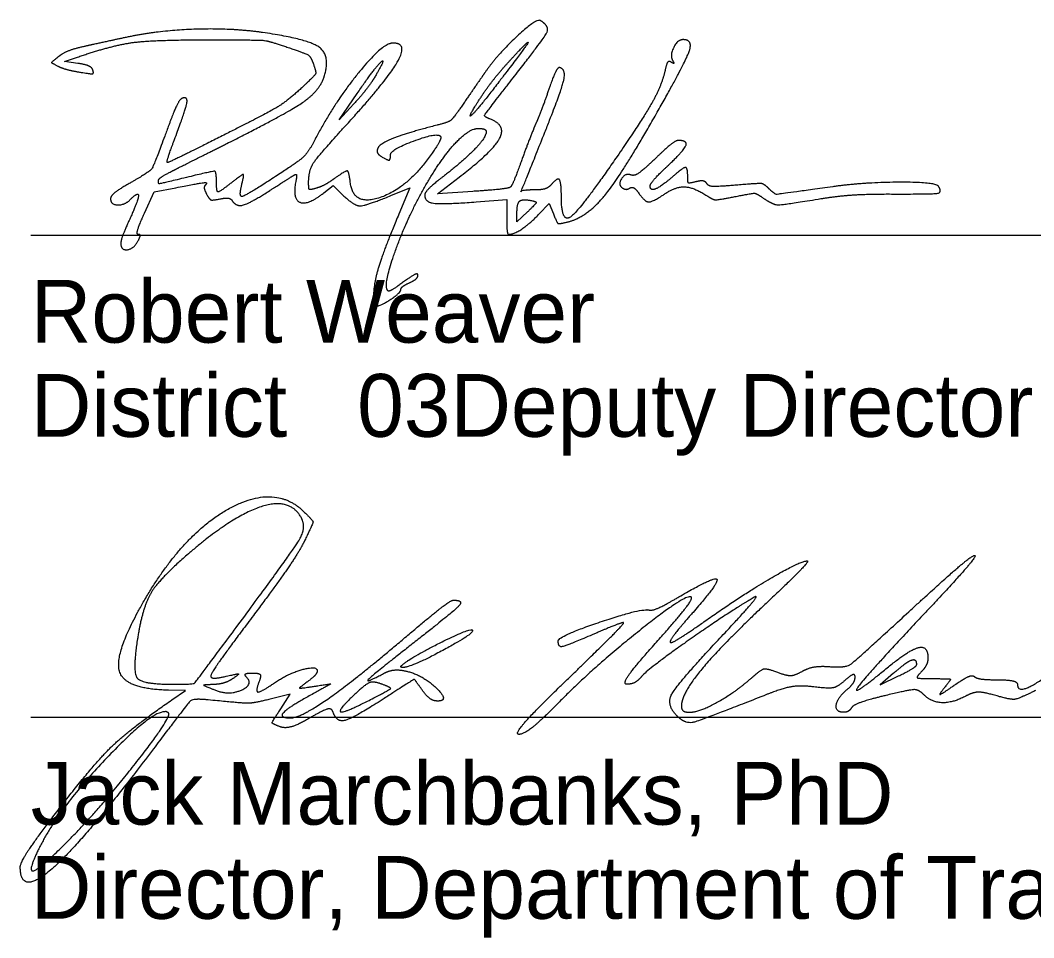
# Model space of a CAD drawing. Extents: x 0 to 34, y 0 to 22.
# Drawn here: x 24.504 to 26.766, y 6.683 to 8.729 of the extents above; entities that cross this region are included whole.
import ezdxf

# ---------------------------------------------------------------- set-up
doc = ezdxf.new("R2010")
doc.units = 0
doc.layers.add('SH_Data', color=7, linetype='Continuous')
doc.layers.add('SH_Text', color=7, linetype='Continuous')

msp = doc.modelspace()

# ---------------------------------------------------------------- linework, layer by layer
at = {"layer": 'SH_Data'}
for p, q in [((24.5279, 8.2504), (28.0279, 8.2504)), ((24.5279, 7.1754), (28.0279, 7.1754))]:
    msp.add_line(p, q, dxfattribs=at)
at = {"layer": 'SH_Text'}
for p, q in [((24.9902, 7.3804), (24.9902, 7.3804)), ((25.3555, 7.2906), (25.3555, 7.2906)), ((26.5045, 7.2926), (26.5045, 7.2926)), ((25.7273, 7.2615), (25.7273, 7.2615)), ((25.3107, 7.2489), (25.3107, 7.2489))]:
    msp.add_line(p, q, dxfattribs=at)
for points in [[(24.633, 8.6331), (24.6031, 8.6371), (24.6297, 8.6463)], [(25.2486, 8.5429), (25.2161, 8.5072), (25.2562, 8.5661)], [(25.5145, 8.3477), (25.4354, 8.3425), (25.484, 8.3797)], [(24.7817, 8.2993), (24.8033, 8.3468), (24.8517, 8.356)], [(25.1816, 8.3443), (25.2022, 8.3605), (25.223, 8.3405)], [(25.3313, 8.3383), (25.3738, 8.3558), (25.3489, 8.2967)], [(25.5215, 8.3243), (25.5897, 8.3294), (25.5897, 8.2907)], [(25.636, 8.3019), (25.6126, 8.2795), (25.6126, 8.3003)], [(25.6617, 8.297), (25.6841, 8.3205), (25.6938, 8.2974)], [(26.4527, 7.2729), (26.4232, 7.2473), (26.4638, 7.267)], [(24.8425, 7.2135), (24.8732, 7.2347), (24.8354, 7.2353)], [(25.0855, 7.1936), (25.1067, 7.226), (25.0649, 7.2159)]]:
    msp.add_lwpolyline(points, dxfattribs=at)
for points in [[(25.6652, 8.7286), (25.6562, 8.7341), (25.5688, 8.6526), (25.5414, 8.6131)], [(25.5906, 8.5834), (25.6722, 8.6878), (25.6864, 8.7155), (25.6652, 8.7286)], [(25.0448, 8.7021), (24.9729, 8.7123), (24.8089, 8.7061), (24.7364, 8.6904)], [(24.6297, 8.6463), (24.708, 8.6734), (24.8025, 8.686), (24.9269, 8.6858)], [(24.7364, 8.6904), (24.7092, 8.6845), (24.6689, 8.6758), (24.647, 8.6709)], [(24.9269, 8.6858), (25.0364, 8.6857), (25.059, 8.6835), (25.1021, 8.6688)], [(25.1825, 8.6036), (25.1974, 8.6505), (25.1452, 8.6879), (25.0448, 8.7021)], [(25.9279, 8.5283), (25.9878, 8.6342), (26.006, 8.6862), (25.9834, 8.6862)], [(25.9834, 8.6862), (25.9708, 8.6862), (25.9533, 8.6501), (25.9604, 8.6387)], [(24.647, 8.6709), (24.625, 8.6661), (24.5995, 8.656), (24.5903, 8.6485)], [(25.1021, 8.6688), (25.1418, 8.6552), (25.1529, 8.6479), (25.1587, 8.6312)], [(25.3356, 8.6785), (25.3122, 8.6782), (25.202, 8.5412), (25.161, 8.4614)], [(25.2278, 8.4914), (25.3216, 8.5939), (25.3705, 8.6789), (25.3356, 8.6785)], [(25.6154, 8.6594), (25.6437, 8.6891), (25.6282, 8.6649), (25.5724, 8.592)], [(24.5903, 8.6485), (24.5739, 8.6353), (24.5739, 8.6348), (24.5883, 8.6272)], [(25.2562, 8.5661), (25.2954, 8.6235), (25.3225, 8.6486), (25.2949, 8.6019)], [(25.526, 8.5482), (25.5441, 8.5768), (25.5835, 8.6258), (25.6154, 8.6594)], [(25.9569, 8.6358), (25.9516, 8.6391), (25.9465, 8.633), (25.9436, 8.6198)], [(25.9604, 8.6387), (25.9633, 8.6339), (25.9619, 8.6327), (25.9569, 8.6358)], [(24.5883, 8.6272), (24.5964, 8.6229), (24.6181, 8.6169), (24.6364, 8.6139)], [(24.6663, 8.6187), (24.6644, 8.6244), (24.6494, 8.6309), (24.633, 8.6331)], [(24.6364, 8.6139), (24.6627, 8.6095), (24.669, 8.6105), (24.6663, 8.6187)], [(25.1587, 8.6312), (25.1649, 8.6134), (25.1627, 8.6075), (25.1432, 8.5889)], [(25.6749, 8.4796), (25.7116, 8.5721), (25.7225, 8.6191), (25.7083, 8.6238)], [(25.7083, 8.6238), (25.7044, 8.6251), (25.6938, 8.6046), (25.6847, 8.5781)], [(25.9436, 8.6198), (25.9358, 8.5847), (25.8955, 8.512), (25.8362, 8.4259)], [(24.965, 8.4542), (25.0974, 8.5206), (25.1725, 8.5722), (25.1825, 8.6036)], [(25.2949, 8.6019), (25.2874, 8.5891), (25.2665, 8.5625), (25.2486, 8.5429)], [(25.5414, 8.6131), (25.5324, 8.6001), (25.5116, 8.5701), (25.4953, 8.5464)], [(25.1432, 8.5889), (25.1048, 8.5522), (25.0562, 8.5222), (24.9441, 8.466)], [(25.5724, 8.592), (25.5259, 8.5312), (25.4994, 8.5062), (25.526, 8.5482)], [(25.552, 8.5093), (25.5386, 8.5143), (25.5425, 8.5218), (25.5906, 8.5834)], [(25.6847, 8.5781), (25.6757, 8.5517), (25.6623, 8.5163), (25.655, 8.4995)], [(24.866, 8.5554), (24.8608, 8.5537), (24.8472, 8.5267), (24.8358, 8.4954)], [(24.8485, 8.4633), (24.873, 8.5284), (24.879, 8.5598), (24.866, 8.5554)], [(25.4953, 8.5464), (25.471, 8.511), (25.4601, 8.5019), (25.4344, 8.4954)], [(25.7247, 8.2793), (25.7685, 8.2896), (25.8483, 8.3874), (25.9279, 8.5283)], [(25.484, 8.3797), (25.5588, 8.437), (25.5895, 8.4955), (25.552, 8.5093)], [(24.8358, 8.4954), (24.803, 8.4056), (24.7932, 8.3911), (24.7476, 8.3654)], [(25.1478, 8.3677), (25.1478, 8.3944), (25.1688, 8.4268), (25.2278, 8.4914)], [(25.4344, 8.4954), (25.3709, 8.4793), (25.3059, 8.4539), (25.302, 8.4437)], [(25.4127, 8.3675), (25.4464, 8.4248), (25.506, 8.4881), (25.5263, 8.4881)], [(25.544, 8.4805), (25.544, 8.4684), (25.4939, 8.4163), (25.4486, 8.3813)], [(25.5263, 8.4881), (25.536, 8.4881), (25.544, 8.4847), (25.544, 8.4805)], [(25.6531, 8.351), (25.6219, 8.351), (25.6205, 8.3428), (25.6749, 8.4796)], [(25.655, 8.4995), (25.6478, 8.4828), (25.6332, 8.4451), (25.6226, 8.4157)], [(24.8327, 8.4119), (24.8308, 8.4119), (24.8379, 8.4351), (24.8485, 8.4633)], [(24.9441, 8.466), (24.8848, 8.4362), (24.8347, 8.4119), (24.8327, 8.4119)], [(25.161, 8.4614), (25.1469, 8.4339), (25.1228, 8.4124), (25.0619, 8.373)], [(25.3307, 8.4298), (25.3307, 8.4409), (25.4335, 8.4793), (25.4416, 8.4712)], [(25.4416, 8.4712), (25.4443, 8.4685), (25.4361, 8.4513), (25.4235, 8.433)], [(25.972, 8.4614), (25.9672, 8.4614), (25.9442, 8.4431), (25.921, 8.4207)], [(25.9487, 8.4044), (25.9845, 8.438), (25.9941, 8.4614), (25.972, 8.4614)], [(24.845, 8.394), (24.8628, 8.403), (24.9168, 8.4301), (24.965, 8.4542)], [(25.302, 8.4437), (25.2998, 8.4379), (25.3028, 8.4302), (25.3086, 8.4265)], [(25.4235, 8.433), (25.371, 8.3566), (25.2471, 8.3126), (25.2407, 8.3681)], [(25.3086, 8.4265), (25.3237, 8.4169), (25.3307, 8.418), (25.3307, 8.4298)], [(25.6226, 8.4157), (25.612, 8.3864), (25.6012, 8.3602), (25.5985, 8.3576)], [(25.8362, 8.4259), (25.754, 8.3067), (25.7117, 8.2758), (25.7117, 8.3353)], [(25.921, 8.4207), (25.8952, 8.3959), (25.8745, 8.3816), (25.8677, 8.3842)], [(24.8126, 8.3719), (24.8126, 8.3751), (24.8272, 8.385), (24.845, 8.394)], [(24.9421, 8.37), (24.9421, 8.3924), (24.9348, 8.3932), (24.8697, 8.3775)], [(25.2407, 8.3681), (25.2378, 8.3929), (25.2305, 8.3941), (25.2028, 8.3745)], [(25.9097, 8.3596), (25.9097, 8.3641), (25.9273, 8.3843), (25.9487, 8.4044)], [(25.9936, 8.3806), (25.9936, 8.4013), (25.9833, 8.401), (25.9588, 8.3795)], [(24.8697, 8.3775), (24.8166, 8.3647), (24.8126, 8.3643), (24.8126, 8.3719)], [(24.8517, 8.356), (24.9082, 8.3668), (24.9237, 8.3681), (24.917, 8.3614)], [(24.9747, 8.3662), (24.9492, 8.3462), (24.9421, 8.347), (24.9421, 8.37)], [(24.9986, 8.3624), (25.0044, 8.3854), (25, 8.3861), (24.9747, 8.3662)], [(25.0619, 8.373), (25.0073, 8.3377), (24.9917, 8.3351), (24.9986, 8.3624)], [(25.0609, 8.3495), (25.0857, 8.3654), (25.1097, 8.3807), (25.1144, 8.3835)], [(25.1144, 8.3835), (25.1199, 8.3869), (25.1216, 8.3822), (25.1192, 8.3697)], [(25.1192, 8.3697), (25.1116, 8.3303), (25.146, 8.3163), (25.1816, 8.3443)], [(25.165, 8.3549), (25.1507, 8.3508), (25.1478, 8.3529), (25.1478, 8.3677)], [(25.2028, 8.3745), (25.1914, 8.3664), (25.1744, 8.3576), (25.165, 8.3549)], [(25.3247, 8.1259), (25.3131, 8.1374), (25.3712, 8.297), (25.4127, 8.3675)], [(25.4486, 8.3813), (25.4257, 8.3636), (25.4069, 8.3447), (25.4069, 8.3392)], [(25.7117, 8.3353), (25.7117, 8.3689), (25.7028, 8.3793), (25.6887, 8.3623)], [(25.8677, 8.3842), (25.8545, 8.3893), (25.837, 8.3621), (25.8488, 8.3548)], [(25.9588, 8.3795), (25.9346, 8.3585), (25.9097, 8.3484), (25.9097, 8.3596)], [(26.0121, 8.3692), (25.9968, 8.3654), (25.9936, 8.3674), (25.9936, 8.3806)], [(26.0361, 8.3652), (26.033, 8.3702), (26.0227, 8.3719), (26.0121, 8.3692)], [(26.5532, 8.3591), (26.5475, 8.3684), (26.3855, 8.3678), (26.3174, 8.3582)], [(24.7476, 8.3654), (24.7247, 8.3525), (24.7059, 8.3371), (24.7059, 8.3312)], [(24.917, 8.3614), (24.9144, 8.3587), (24.9158, 8.3498), (24.9202, 8.3415)], [(24.9766, 8.3279), (24.9857, 8.3131), (25.0169, 8.3211), (25.0609, 8.3495)], [(25.5985, 8.3576), (25.5958, 8.355), (25.558, 8.3505), (25.5145, 8.3477)], [(25.6887, 8.3623), (25.6835, 8.3561), (25.6675, 8.351), (25.6531, 8.351)], [(25.8488, 8.3548), (25.853, 8.3522), (25.8601, 8.3524), (25.8646, 8.3552)], [(25.8646, 8.3552), (25.8692, 8.3579), (25.8779, 8.353), (25.8841, 8.3442)], [(25.8841, 8.3442), (25.898, 8.3243), (25.9146, 8.3239), (25.9432, 8.3427)], [(25.9432, 8.3427), (25.9677, 8.3589), (26.0075, 8.3568), (26.0368, 8.3378)], [(26.1016, 8.3616), (26.06, 8.3581), (26.0398, 8.3592), (26.0361, 8.3652)], [(26.099, 8.3361), (26.1385, 8.3439), (26.1471, 8.3434), (26.1622, 8.3328)], [(26.1744, 8.3541), (26.1639, 8.3645), (26.1519, 8.3658), (26.1016, 8.3616)], [(26.3174, 8.3582), (26.1955, 8.3411), (26.1876, 8.3409), (26.1744, 8.3541)], [(26.4481, 8.3419), (26.5395, 8.3416), (26.5618, 8.3452), (26.5532, 8.3591)], [(24.7059, 8.3312), (24.7059, 8.3181), (24.7374, 8.3169), (24.75, 8.3295)], [(24.75, 8.3295), (24.7685, 8.348), (24.7678, 8.3277), (24.7486, 8.2858)], [(24.9202, 8.3415), (24.9264, 8.33), (24.9334, 8.3275), (24.9502, 8.3309)], [(24.9502, 8.3309), (24.9622, 8.3333), (24.9741, 8.3319), (24.9766, 8.3279)], [(25.223, 8.3405), (25.2489, 8.3157), (25.2749, 8.3152), (25.3313, 8.3383)], [(25.4069, 8.3392), (25.4069, 8.3239), (25.4468, 8.3187), (25.5215, 8.3243)], [(25.6126, 8.3003), (25.6126, 8.3216), (25.6252, 8.3313), (25.647, 8.3268)], [(25.647, 8.3268), (25.6569, 8.3248), (25.6546, 8.3197), (25.636, 8.3019)], [(26.0368, 8.3378), (26.0504, 8.329), (26.0614, 8.3287), (26.099, 8.3361)], [(26.1622, 8.3328), (26.1836, 8.3178), (26.2066, 8.3176), (26.2907, 8.3315)], [(26.2907, 8.3315), (26.3263, 8.3374), (26.3971, 8.3421), (26.4481, 8.3419)], [(24.7676, 8.2519), (24.7635, 8.2519), (24.7699, 8.2733), (24.7817, 8.2993)], [(24.7486, 8.2858), (24.7377, 8.2619), (24.7288, 8.2377), (24.7288, 8.232)], [(25.3489, 8.2967), (25.3169, 8.2207), (25.2926, 8.142), (25.2926, 8.114)], [(25.5897, 8.2907), (25.5897, 8.2693), (25.5916, 8.2519), (25.5939, 8.2519)], [(25.5939, 8.2519), (25.6055, 8.2519), (25.6418, 8.2761), (25.6617, 8.297)], [(25.6938, 8.2974), (25.7022, 8.2773), (25.7062, 8.275), (25.7247, 8.2793)], [(24.7288, 8.232), (24.7288, 8.2159), (24.7577, 8.2195), (24.7669, 8.2367)], [(24.7669, 8.2367), (24.7719, 8.2461), (24.7722, 8.2519), (24.7676, 8.2519)], [(25.3917, 8.161), (25.3917, 8.1656), (25.3773, 8.1589), (25.3598, 8.146)], [(25.3598, 8.146), (25.3423, 8.1331), (25.3265, 8.1241), (25.3247, 8.1259)], [(25.3536, 8.1287), (25.3536, 8.1323), (25.3621, 8.1391), (25.3726, 8.1439)], [(25.3726, 8.1439), (25.3831, 8.1486), (25.3917, 8.1563), (25.3917, 8.161)], [(25.2983, 8.0919), (25.3085, 8.092), (25.3536, 8.122), (25.3536, 8.1287)], [(25.2926, 8.114), (25.2926, 8.1018), (25.2952, 8.0919), (25.2983, 8.0919)], [(24.7789, 7.4312), (24.8651, 7.5816), (25.0732, 7.6976), (25.1389, 7.6319)], [(25.1299, 7.6227), (25.104, 7.6648), (24.9779, 7.6236), (24.8825, 7.542)], [(24.9902, 7.3804), (25.1115, 7.5439), (25.144, 7.6001), (25.1299, 7.6227)], [(25.1389, 7.6319), (25.1577, 7.6132), (25.1577, 7.6081), (25.1394, 7.5697)], [(25.1394, 7.5697), (25.1284, 7.5467), (25.0767, 7.4711), (25.0245, 7.4018)], [(24.8825, 7.542), (24.8159, 7.4849), (24.7771, 7.4208), (24.766, 7.3496)], [(26.4869, 7.4101), (26.5619, 7.4792), (26.6279, 7.5358), (26.6336, 7.5359)], [(26.6336, 7.5359), (26.6394, 7.5359), (26.5873, 7.4758), (26.518, 7.4022)], [(26.0326, 7.3897), (26.1131, 7.4463), (26.2445, 7.5235), (26.2602, 7.5235)], [(26.2602, 7.5235), (26.265, 7.5235), (26.2237, 7.4809), (26.1684, 7.4288)], [(25.9736, 7.4432), (26.0524, 7.4893), (26.0646, 7.4761), (26.0054, 7.4088)], [(26.0017, 7.4429), (25.9921, 7.4525), (25.7824, 7.2856), (25.7045, 7.2063)], [(26.142, 7.4425), (26.0929, 7.4147), (25.9046, 7.2825), (25.8914, 7.2665)], [(25.908, 7.4139), (25.9136, 7.4121), (25.9431, 7.4253), (25.9736, 7.4432)], [(25.9239, 7.3425), (25.9702, 7.3943), (26.0052, 7.4394), (26.0017, 7.4429)], [(26.0768, 7.3635), (26.123, 7.4128), (26.1523, 7.4483), (26.142, 7.4425)], [(24.8354, 7.2353), (24.7375, 7.237), (24.7141, 7.3182), (24.7789, 7.4312)], [(25.369, 7.3577), (25.4194, 7.4006), (25.4649, 7.4357), (25.4701, 7.4358)], [(25.4701, 7.4358), (25.495, 7.4363), (25.4716, 7.4108), (25.3857, 7.3435)], [(26.1684, 7.4288), (26.0687, 7.3351), (25.9795, 7.2269), (25.9795, 7.2)], [(25.0245, 7.4018), (24.9722, 7.3324), (24.9295, 7.2718), (24.9295, 7.267)], [(25.7047, 7.3454), (25.7049, 7.3559), (25.8923, 7.4191), (25.908, 7.4139)], [(26.0054, 7.4088), (25.9774, 7.377), (25.9545, 7.3473), (25.9545, 7.3428)], [(26.3119, 7.2877), (26.3453, 7.2849), (26.3688, 7.3013), (26.4869, 7.4101)], [(26.518, 7.4022), (26.3885, 7.2646), (26.3564, 7.2174), (26.4386, 7.2851)], [(24.844, 7.2485), (24.8907, 7.2485), (24.8953, 7.2526), (24.9902, 7.3804)], [(25.7273, 7.2615), (25.7983, 7.33), (25.8537, 7.386), (25.8502, 7.386)], [(25.8502, 7.386), (25.8468, 7.386), (25.8178, 7.3748), (25.7857, 7.361)], [(25.9545, 7.3428), (25.9545, 7.3384), (25.9896, 7.3595), (26.0326, 7.3897)], [(24.766, 7.3496), (24.7545, 7.2762), (24.776, 7.2485), (24.844, 7.2485)], [(25.1076, 7.1735), (25.1307, 7.1735), (25.2567, 7.2623), (25.369, 7.3577)], [(25.3555, 7.2906), (25.3759, 7.3084), (25.5079, 7.3742), (25.5131, 7.3691)], [(25.5131, 7.3691), (25.5193, 7.3629), (25.3767, 7.286), (25.359, 7.286)], [(25.7857, 7.361), (25.7231, 7.3342), (25.7044, 7.3306), (25.7047, 7.3454)], [(25.9697, 7.1779), (25.9445, 7.2031), (25.9734, 7.2532), (26.0768, 7.3635)], [(26.7295, 7.247), (26.7295, 7.2242), (26.8248, 7.2856), (26.8951, 7.3538)], [(25.3857, 7.3435), (25.2925, 7.2705), (25.271, 7.2489), (25.315, 7.2724)], [(25.8581, 7.2485), (25.8478, 7.2485), (25.8767, 7.2898), (25.9239, 7.3425)], [(26.4386, 7.2851), (26.487, 7.325), (26.5295, 7.3354), (26.5295, 7.3073)], [(26.5295, 7.3073), (26.5295, 7.2983), (26.5227, 7.2843), (26.5145, 7.276)], [(25.0736, 7.2529), (25.1025, 7.2727), (25.167, 7.2902), (25.167, 7.2782)], [(25.359, 7.286), (25.3542, 7.286), (25.3526, 7.2881), (25.3555, 7.2906)], [(26.137, 7.2635), (26.1573, 7.2815), (26.1701, 7.2842), (26.1939, 7.2752)], [(26.2489, 7.2772), (26.2623, 7.2848), (26.2906, 7.2895), (26.3119, 7.2877)], [(26.5045, 7.2926), (26.5045, 7.3061), (26.4804, 7.2969), (26.4527, 7.2729)], [(26.4638, 7.267), (26.4862, 7.2778), (26.5045, 7.2893), (26.5045, 7.2926)], [(24.9295, 7.267), (24.9295, 7.2622), (24.9449, 7.2619), (24.9638, 7.2663)], [(24.9795, 7.2616), (24.9692, 7.2546), (24.9495, 7.2484), (24.9357, 7.2479)], [(24.9399, 7.2352), (24.9698, 7.2233), (25.026, 7.2478), (25.0086, 7.2652)], [(24.9638, 7.2663), (24.9894, 7.2722), (24.9934, 7.271), (24.9795, 7.2616)], [(25.0086, 7.2652), (25.004, 7.2698), (25.0103, 7.2735), (25.0225, 7.2735)], [(25.0225, 7.2735), (25.037, 7.2735), (25.0422, 7.2671), (25.0375, 7.2548)], [(25.167, 7.2782), (25.167, 7.2737), (25.1572, 7.2629), (25.1453, 7.2542)], [(25.315, 7.2724), (25.3276, 7.2792), (25.3515, 7.2813), (25.3681, 7.2771)], [(25.4011, 7.2357), (25.3843, 7.2597), (25.3822, 7.2593), (25.3165, 7.2169)], [(25.3681, 7.2771), (25.4042, 7.2679), (25.4625, 7.211), (25.4358, 7.211)], [(25.617, 7.1367), (25.6067, 7.1369), (25.6563, 7.1931), (25.7273, 7.2615)], [(25.8914, 7.2665), (25.8831, 7.2566), (25.8682, 7.2485), (25.8581, 7.2485)], [(25.9975, 7.186), (26.0192, 7.186), (26.1006, 7.2312), (26.137, 7.2635)], [(26.1939, 7.2752), (26.2141, 7.2675), (26.2329, 7.2682), (26.2489, 7.2772)], [(26.367, 7.2645), (26.367, 7.2716), (26.3568, 7.2682), (26.3444, 7.257)], [(26.3482, 7.236), (26.3585, 7.2446), (26.367, 7.2574), (26.367, 7.2645)], [(26.5145, 7.276), (26.5028, 7.2643), (26.5087, 7.261), (26.541, 7.261)], [(26.541, 7.261), (26.5785, 7.261), (26.5809, 7.2589), (26.5654, 7.2396)], [(26.5871, 7.2455), (26.6085, 7.2605), (26.6293, 7.2696), (26.6332, 7.2656)], [(26.6332, 7.2656), (26.6371, 7.2617), (26.6604, 7.2585), (26.6849, 7.2585)], [(26.6849, 7.2585), (26.7094, 7.2585), (26.7295, 7.2533), (26.7295, 7.247)], [(24.9357, 7.2479), (24.9133, 7.247), (24.9138, 7.2457), (24.9399, 7.2352)], [(25.0375, 7.2548), (25.0285, 7.2315), (25.0414, 7.2308), (25.0736, 7.2529)], [(25.1453, 7.2542), (25.1264, 7.2404), (25.1284, 7.2391), (25.161, 7.244)], [(25.161, 7.244), (25.1977, 7.2496), (25.1976, 7.2493), (25.1522, 7.2242)], [(25.3107, 7.2489), (25.2935, 7.2552), (25.277, 7.2501), (25.2576, 7.2324)], [(25.2826, 7.2126), (25.329, 7.2363), (25.3325, 7.2409), (25.3107, 7.2489)], [(25.4358, 7.211), (25.4262, 7.211), (25.4106, 7.2221), (25.4011, 7.2357)], [(26.2749, 7.2425), (26.2457, 7.2463), (26.2058, 7.2398), (26.1693, 7.2254)], [(26.3444, 7.257), (26.3287, 7.2428), (26.3075, 7.2384), (26.2749, 7.2425)], [(26.3412, 7.186), (26.3229, 7.186), (26.3274, 7.2188), (26.3482, 7.236)], [(26.5199, 7.2256), (26.5088, 7.2367), (26.4887, 7.2362), (26.4355, 7.2235)], [(26.5654, 7.2396), (26.5533, 7.2246), (26.5598, 7.2264), (26.5871, 7.2455)], [(24.5916, 6.9713), (24.6692, 7.0717), (24.7493, 7.149), (24.8425, 7.2135)], [(24.9237, 7.2136), (24.8903, 7.2169), (24.8786, 7.2064), (24.8019, 7.1048)], [(25.0649, 7.2159), (25.0246, 7.2061), (25.0023, 7.2058), (24.9237, 7.2136)], [(25.1522, 7.2242), (25.1011, 7.196), (25.0814, 7.1735), (25.1076, 7.1735)], [(25.3165, 7.2169), (25.2476, 7.1726), (25.2101, 7.1628), (25.202, 7.1872)], [(25.2576, 7.2324), (25.2133, 7.1919), (25.2246, 7.183), (25.2826, 7.2126)], [(26.1693, 7.2254), (26.0233, 7.1677), (25.9882, 7.1594), (25.9697, 7.1779)], [(26.4355, 7.2235), (26.3972, 7.2143), (26.3629, 7.2021), (26.3594, 7.1964)], [(26.6162, 7.2231), (26.5854, 7.2066), (26.5376, 7.2079), (26.5199, 7.2256)], [(26.6807, 7.2232), (26.6538, 7.2309), (26.6307, 7.2308), (26.6162, 7.2231)], [(26.7698, 7.2345), (26.7324, 7.216), (26.7138, 7.2136), (26.6807, 7.2232)], [(25.0843, 7.1536), (25.0661, 7.1606), (25.0662, 7.1642), (25.0855, 7.1936)], [(25.202, 7.1872), (25.1991, 7.1957), (25.1799, 7.1905), (25.1508, 7.1734)], [(25.7045, 7.2063), (25.6667, 7.1678), (25.6273, 7.1365), (25.617, 7.1367)], [(25.9795, 7.2), (25.9795, 7.1923), (25.9876, 7.186), (25.9975, 7.186)], [(26.3594, 7.1964), (26.3559, 7.1907), (26.3477, 7.186), (26.3412, 7.186)], [(24.8354, 7.1842), (24.8145, 7.2051), (24.596, 6.9795), (24.5497, 6.8891)], [(24.6198, 6.9079), (24.6874, 6.9769), (24.8431, 7.1765), (24.8354, 7.1842)], [(25.1508, 7.1734), (25.1252, 7.1583), (25.0953, 7.1494), (25.0843, 7.1536)], [(24.8019, 7.1048), (24.6496, 6.9027), (24.5045, 6.774), (24.5045, 6.841)], [(24.5045, 6.841), (24.5045, 6.8507), (24.5437, 6.9093), (24.5916, 6.9713)], [(24.5497, 6.8891), (24.5184, 6.8282), (24.55, 6.8366), (24.6198, 6.9079)]]:
    msp.add_open_spline(points, degree=2, dxfattribs=at)

# ---------------------------------------------------------------- texts
for s, p in [('Robert Weaver', (24.5279, 8.0104)), ('District       Deputy Director', (24.5279, 7.8004)), ('              03', (24.5279, 7.8004)), ('Jack Marchbanks, PhD', (24.5279, 6.9354)), ('Director, Department of Transportation', (24.5279, 6.7254))]:
    msp.add_text(s, height=0.14, dxfattribs=at).set_placement(p)

doc.saveas('drawing.dxf')
